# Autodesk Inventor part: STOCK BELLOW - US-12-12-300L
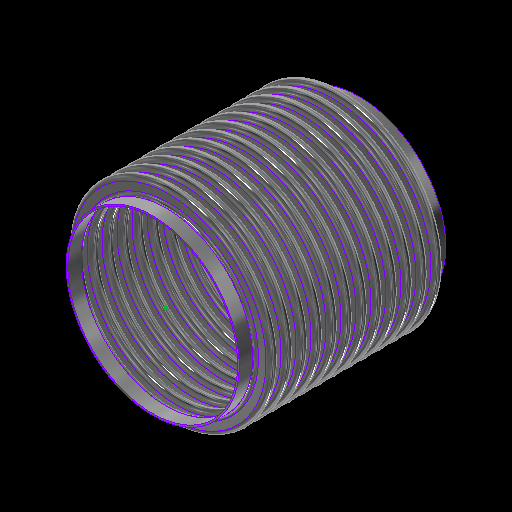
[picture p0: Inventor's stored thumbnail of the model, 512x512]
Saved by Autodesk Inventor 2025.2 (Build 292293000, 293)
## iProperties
Category: 16 GA (0.060 THICK)
RuleStatus: InUse
Created: 2024-01
Part Number: STOCK BELLOW - US-12-12-300L
Project: =STOCK BELLOWS: <Stock Number><SFILL>
Material: ASTM A240-304
Description: =STOCK BELLOWS: <Stock Number>, <SID_> I.D., <SOD_> O.D., <SPLY_> PLY, <Category>, <SNET_CONS> CONS.<PITCH_><STANGENT_> TANGENT<SFILL>
Document SubType Name: Sheet Metal
Designer: GS
Stock Number: U.S-12-12-300L
Surface Area: 20995.3 cm^2
Volume: 3171.06 cm^3
Sheet Metal Rule: Default
Appearance: STAINLESS STEEL
Mass: 25550.1 g
Density: 8.05729 g/cm^3
THK: 0.036
ID: 3.500
OD: 4.250
CONS_: 2
PITCH: 0.500
TANGENT: 0.500
BELLOWS_UPSET: 0.000
d79: 1.000
d82: 1.000
d83: 26.000
d84: 24.000
d174: 8
d214: 8
STHK_: 0.060
SID_: 12.750
SOD_: 15.250
SPITCH_: 1.125
STANGENT__: 1.000
SBELLOWS_UPSET_: 0.000
SDIFF_TAN: 1.000
d252: 2
d275: 2
d287: 0.050
d289: 0.500
d290: 0.000
SOD_NECK: 13
PLY: 1
PSET: 4.178
PBAR: 1.035
COUNTER: 1.500
NET_TUBE: 3.071
CONS: 2
S_CONS: 0
NET_CONS: 2
ID_M: 88.90 mm
OD_M: 107.95 mm
THK_M: 0.91 mm
ID_U: 3.500 in
OD_U: 4.250 in
THK_U: 0.036 in
TANGENT2: 0.500
TAN_TO_TAN: 1.000 in
d80: 2.571
d81: 10
SID: 2.375
SCONS_: 12
SPITCH: 0.250
STANGENT_: 1.000
SBELLOWS_UPSET: 0.000
SNET_CONS: 12
SS_CONS: 0
SCONS: 8
d190: 8
d191: 1
d192: 1
d193: 8
d194: 0
SIZE: 12.00
PRESSURE: 300
d230: 8
STANGENT: 4.000
SPLY_: 2
d233: 8
d234: 0
d263: 2
d265: 1
d268: 2
d269: 0
d286: 2
d288: 1
d291: 2
d292: 0
SREROLL: 0.750
BLETP: 1.000 ul
PRES_Copy: 85
MATTABLE: 20 GA (0.036 THICK)
PART_NUMBER: U.S-12-12-300L
PITCH_: =, <SPITCH_> PITCH,
CFILL: .
SFILL: .
MESH: ,
COMP: 2.36
EXT: 1.18
LAT: 0.76
ANG: 573
ASR: 4950
LSR: 7985
ANSR: 2116
PRES: 300
COMPM: 23.6
EXTM: 11.8
LATM: 7.60
ASRM: 866.894
PRESM: 20.684
LSRM: 1398.413
ANSRM: 370.575
TEMPMIN: 20
TEMPMAX: 800
TEMPMINM: -7
TEMPMAXM: 427
WEIGHTM: 25.550
WEIGHT: 56.328
Author: GS
Keywords: 20 GA (0.036 THICK)
Comments: =STOCK BELLOW - <STOCK NUMBER>
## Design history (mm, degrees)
sketch "Sketch2"
  geometry: L1 (0, -177.245)-(0, 562.856) reference; L2 (45.364, 0)-(44.45, 0); L3 (48.082, -2.718)-(50.343, -2.718); L4 (48.082, -3.632)-(50.343, -3.632); L5 (50.343, -9.982)-(48.082, -9.982); L6 (50.343, -9.068)-(48.082, -9.068); L7 (45.364, -12.7)-(44.45, -12.7); L8 (48.082, 0)-(48.082, -12.7); L9 (50.343, -6.35)-(53.975, -6.35); L10 (44.45, 0)-(44.45, -12.7); L11 (20.376, 102.841)-(20.376, 101.926); L12 (58.262, 457.127)-(58.262, 349.177); L13 (58.262, 444.427)-(58.262, 336.477); L14 (93.133, -58.817)-(93.133, -71.517); L15 (118.746, -66.401)-(118.746, -66.401); L16 (50.343, -9.068)-(50.343, -9.982); L17 (48.082, -9.068)-(48.082, -9.982); L18 (48.082, -9.525)-(50.343, -9.525); L19 (53.975, 0)-(53.975, -12.7); L20 (-50.343, -9.068)-(-50.343, -9.982); L21 (-50.343, -2.718)-(-48.082, -2.718); L22 (-50.343, -3.632)-(-48.082, -3.632); L23 (-48.082, -9.068)-(-50.343, -9.068); L24 (-50.343, -9.525)-(-48.082, -9.525); L25 (-48.082, -9.982)-(-50.343, -9.982); L26 (-48.082, -9.068)-(-48.082, -9.982); L27 (-44.45, 0.653)-(-44.45, -12.047); L28 (-48.082, -6.35)-(-44.45, -6.35); L29 (-50.343, 0.653)-(-50.343, -12.7); L30 (-53.061, 0)-(-53.975, 0); L31 (-53.975, 0)-(-53.975, -12.7); L32 (-53.061, -12.7)-(-53.975, -12.7); A1 r 2.718 centre (48.082, 0) between (45.364, 0) and (48.082, -2.718); A2 r 3.632 centre (48.082, 0) between (44.45, 0) and (48.082, -3.632); A3 r 3.632 centre (50.343, -6.35) between (50.343, -9.982) and (50.343, -2.718); A4 r 2.718 centre (50.343, -6.35) between (50.343, -9.068) and (50.343, -3.632); A5 r 2.718 centre (48.082, -12.7) between (48.082, -9.982) and (45.364, -12.7); A6 r 3.632 centre (48.082, -12.7) between (48.082, -9.068) and (44.45, -12.7); A7 r 3.175 centre (50.343, -6.35) between (50.343, -9.525) and (53.518, -6.35); A8 r 3.175 centre (48.082, -12.7) between (48.082, -9.525) and (44.907, -12.7); A9 r 2.718 centre (-50.343, -12.7) between (-50.343, -9.982) and (-53.061, -12.7); A10 r 2.718 centre (-48.082, -6.35) between (-48.082, -9.068) and (-48.082, -3.632); A11 r 3.175 centre (-48.082, -6.35) between (-48.082, -9.525) and (-44.907, -6.35); A12 r 3.632 centre (-48.082, -6.35) between (-48.082, -9.982) and (-48.082, -2.718); A13 r 3.175 centre (-50.343, -12.7) between (-50.343, -9.525) and (-53.518, -12.7); A14 r 3.632 centre (-50.343, -12.7) between (-50.343, -9.068) and (-53.975, -12.7); A15 r 2.718 centre (-50.343, 0) between (-53.061, 0) and (-50.343, -2.718); A16 r 3.632 centre (-50.343, 0) between (-53.975, 0) and (-50.343, -3.632); 10 further points
  constraints: 62 end point, 38 point on circle, 20 tangent, 16 centre point, 12 parallel, 9 midpoint, 7 vertical, 6 coincident, 6 concentric, 6 point on line, 4 equal radius, 4 perpendicular, 3 horizontal, 1 collinear, 1 horizontal alignment, 10 other
  dimensions: "THK" = 0.9144 distance of L11.start L11.end; "ID" = 88.9 distance of L11.end point (20.376, 13.026); "OD" = 107.95 distance of L12.start L12.end; "PITCH" = 12.7 distance of L12.start L13.start; "TANGENT" = 12.7 distance of L14.start L14.end; "BELLOWS_UPSET" = 0 distance of L15.start L15.end; "d43" = 88.9 diameter of L10 L1 (= ID); "d44" = 107.95 diameter of L9.end L1 (= OD); "d45" = 0.9144 distance between parallel lines of L5 L6 (computed from THK, PLY); "d46" = 3.6322 radius of A3 (computed from PITCH, THK, PLY); "UPSET_PITCH" = 12.7 distance of L2.end L7.end (derived); "SIDEWALL_ANGLE" = 360 deg dimension on L3 L9 (derived); "CON_GAP" = 5.4356 distance of point (48.082, -9.068) point (48.082, -3.632) (derived); "TAN1" = 4.98728 dimension on A8 (derived); "TAN2" = 4.98728 dimension on A7 (derived); "LEG1" = 2.2606 distance of L18.start L18.end (derived); "d278" = 0.9144 distance between parallel lines of L25 L23 (derived); "d279" = 3.6322 radius of A12 (derived); "d280" = 12.7 distance of L30.end L31.end (derived); "d281" = 360 deg dimension on L21 L28 (derived); "d282" = 5.4356 distance of point (-50.343, -9.068) point (-50.343, -3.632) (derived); "d283" = 4.98728 dimension on A13 (derived); "d284" = 4.98728 dimension on A11 (derived); "d285" = 2.2606 distance of L24.start L24.end (derived); "d293" = 88.9 diameter of L27 L1 (derived); "d294" = 107.95 diameter of L31 L1 (derived)
  node "Sketch Rectangular Pattern1" dims "d31" = 25.4, "ID" = 88.9
  node "Sketch Rectangular Pattern2" dims "d39" = 25.4, "PITCH" = 12.7
revolve "CONS" stored, may be unused: angle "d48" = 90 deg
node "BELLOW MIDPLANE"
pattern_linear "Rectangular Pattern2" dims "d52" = 12.7 (= UPSET_PITCH)
sketch "Sketch5"
  geometry: C1 r 45.364 at (0, 0) reference; C2 r 44.45 at (0, 0) reference
extrude "TANGENT" new body sketch "Sketch5" distance "d53" = 12.7 (= TANGENT); taper "d54" = 0 deg
revolve "SAMETAN" stored, may be unused: angle "d65" = 90 deg
revolve "DIFFTAN" stored, may be unused: angle "d70" = 90 deg
sketch "Sketch9"
  geometry: L1 (53.319, 0)-(-53.319, 0) reference; L2 (0, -17.78)-(0, 17.78) reference; L3 (38.085, 0)-(-38.085, 0); L4 (38.085, -11.906)-(38.085, 11.906); L5 (25.385, -11.906)-(25.385, 11.906); L6 (13.15, 11.906)-(13.15, -11.906); L7 (-25.385, -11.906)-(-25.385, 11.906); L8 (-38.085, -11.906)-(-38.085, 11.906); L9 (37.291, -11.906)-(37.291, 11.906); L10 (38.085, -11.906)-(37.291, -11.906); L11 (38.085, 11.906)-(37.291, 11.906); L12 (13.546, 11.906)-(12.753, 11.906); L13 (12.753, 11.906)-(12.753, -11.906); L14 (12.753, -11.906)-(13.546, -11.906); L15 (13.546, -11.906)-(13.546, 11.906); L16 (-13.546, 11.906)-(-13.546, -11.906); L17 (-13.15, 11.906)-(-13.15, -11.906); L18 (-13.546, -11.906)-(-12.753, -11.906); L19 (-12.753, -11.906)-(-12.753, 11.906); L20 (-12.753, 11.906)-(-13.546, 11.906); L21 (-38.085, -11.906)-(-37.291, -11.906); L22 (-37.291, -11.906)-(-37.291, 11.906); L23 (-37.291, 11.906)-(-38.085, 11.906); L24 (-38.085, 11.906)-(-38.085, -11.906); L25 (38.085, -0.397)-(-38.085, -0.397); L26 (-38.085, -0.397)-(-38.085, 0.397); L27 (-38.085, 0.397)-(38.085, 0.397); L28 (38.085, 0.397)-(38.085, -0.397); L29 (-38.085, 11.906)-(38.085, 11.906); L30 (38.085, 11.906)-(38.085, 12.7); L31 (38.085, 12.7)-(-38.085, 12.7); L32 (-38.085, 12.7)-(-38.085, 11.906); L33 (38.085, -11.906)-(-38.085, -11.906); L34 (-38.085, -11.906)-(-38.085, -12.7); L35 (-38.085, -12.7)-(38.085, -12.7); L36 (38.085, -12.7)-(38.085, -11.906); 30 further points
  constraints: 68 end point, 13 midpoint, 13 parallel, 8 horizontal, 7 perpendicular, 6 equal length, 3 point on line, 2 vertical, 14 other
  dimensions: "d115" = 23.8125 distance of L4.start L4.end (derived); "d116" = 12.7 distance between parallel lines of L4 L5 (derived); "d117" = 12.23516 distance between parallel lines of L5 L6 (derived); "d125" = 38.53427 distance between parallel lines of L7 L6 (derived); "d127" = 12.7 distance between parallel lines of L8 L7 (derived); "d128" = 24.93516 distance between parallel lines of L6 L4 (derived); "d130" = 76.16943 distance between parallel lines of L8 L4 (derived); "RULER_THK" = 0.79375 distance between parallel lines of L4 L9; "d135" = 0.79375 distance of L13.end L14.end (derived); "d138" = 26.29911 distance of L13.end L16.end (derived); "d143" = 0.79375 distance of L22.end L8.end (derived); "d144" = 0.79375 distance between parallel lines of L27 L25 (derived)
extrude "RULER" join sketch "Sketch9" distance "d149" = 0.79375 (derived); taper "d150" = 0 deg
extrude "BARS" join sketch "Sketch9" distance "d151" = 0.79375 (derived); taper "d152" = 0 deg
pattern_linear "Rectangular Pattern4" dims "d155" = 26.29911 (derived)
sketch "Sketch13"
  geometry: L1 (93.149, -52.467)-(93.149, -77.867); L2 (164.973, 0)-(161.925, 0); L3 (164.973, -28.575)-(161.925, -28.575); L4 (185.007, -22.955)-(170.593, -22.955); L5 (185.007, -19.907)-(170.593, -19.907); L6 (185.007, -14.287)-(193.675, -14.288); L7 (170.593, -5.62)-(185.007, -5.62); L8 (170.593, 0)-(170.593, -28.575); L9 (161.925, 0)-(161.925, -28.575); L10 (58.254, -109.081)-(58.254, -496.431); L11 (58.254, -137.656)-(58.254, -525.006); L12 (58.254, -194.806)-(58.254, -582.156); L13 (58.254, -223.381)-(58.254, -610.731); L14 (58.254, -251.956)-(58.254, -639.306); L15 (58.254, -280.531)-(58.254, -667.881); L16 (58.254, -309.106)-(58.254, -696.456); L17 (58.254, -166.231)-(58.254, -553.581); L18 (20.376, 103.45)-(20.376, 101.926); L19 (170.593, -8.668)-(185.007, -8.668); L20 (0, -856.437)-(0, 263.431) reference; L21 (-38.735, 0)-(232.41, 0) reference; A1 r 5.62 centre (170.593, 0) between (164.973, 0) and (170.593, -5.62); A2 r 5.62 centre (170.593, -28.575) between (170.593, -22.955) and (164.973, -28.575); A3 r 8.668 centre (170.593, -28.575) between (170.593, -19.907) and (161.925, -28.575); A4 r 5.62 centre (185.007, -14.287) between (185.007, -19.907) and (185.007, -8.668); A5 r 8.668 centre (185.007, -14.287) between (185.007, -22.955) and (185.007, -5.62); A6 r 8.668 centre (170.593, 0) between (161.925, 0) and (170.593, -8.668); 6 further points; 1 other entity
  constraints: 38 end point, 15 point on circle, 9 tangent, 6 centre point, 6 parallel, 5 vertical alignment, 4 point on line, 4 vertical, 3 coincident, 3 concentric, 2 collinear, 2 equal radius, 1 horizontal, 1 perpendicular, 23 other
  dimensions: "SBELLOWS_UPSET_" = 0 distance of point (118.762, -66.401) point (118.762, -66.401); "STOTAL_THK_BELLOW__" = 3.048 distance between parallel lines of L4 L5 (derived); "d224" = 8.66775 radius of A5 (derived); "d225" = 28.575 distance of L2.end L3.end (derived); "SSIDEWALL_ANGLE_" = 360 deg dimension on L7 L6 (derived); "SSCON_GAP_" = 11.2395 distance of point (170.593, -19.907) point (170.593, -8.668) (derived); "d235" = 323.85 diameter of L9 L20 (derived); "d236" = 387.35 diameter of L6.end L20 (derived)
  node "Sketch Rectangular Pattern4" dims "d228" = 25.4
  node "Sketch Rectangular Pattern5" dims "d229" = 25.4
revolve "SBELLOW" stored, may be unused: angle "d197" = 90 deg
pattern_linear "Rectangular Pattern5" dims "d204" = 28.575 (derived)
revolve "STANGENT" stored, may be unused: angle "d240" = 90 deg
revolve "SSAMETAN" stored, may be unused: angle "d241" = 90 deg
revolve "SDIFFTAN" stored, may be unused: angle "d246" = 90 deg
revolve "INVCON" stored, may be unused: angle "d295" = 90 deg
pattern_linear "Rectangular Pattern6" dims "d298" = 12.7 (derived)
revolve "INVTANGENT" stored, may be unused: angle "d302" = 90 deg
revolve "INVSAMETAN" stored, may be unused: angle "d307" = 90 deg
revolve "INVDIFFTAN" stored, may be unused: angle "d312" = 90 deg
sketch "ID BELLOW MOUNT CALC"
  geometry: L1 (44.45, 0)-(38.1, 0); L2 (38.1, 0)-(38.1, 12.7); L3 (38.1, 12.7)-(44.45, 12.7); L4 (44.45, 12.7)-(44.45, 0); L5 (36.513, 12.7)-(35.598, 12.7); L6 (35.598, 12.7)-(35.598, 0); L7 (35.598, 0)-(36.513, 0); L8 (36.513, 0)-(36.513, 12.7); L9 (0, -2.54)-(0, 15.24) reference; L10 (-8.89, 0)-(53.34, 0) reference; 1 further point
  constraints: 16 end point, 5 parallel, 2 collinear, 2 horizontal, 2 perpendicular
  dimensions: "d314" = 12.7 distance of L5.end L6.end (derived); "d315" = 0.9144 distance of L5.start L5.end (derived); "IG" = 1.5875 distance between parallel lines of L2 L8; "PIPE_OD" = 88.9 diameter of L4 L9; "PIPE_WALL" = 6.35 distance of L2.end L3.end; "ID_MT_BELLOW" = 71.1962 diameter of L6 L9 (derived)
revolve "CFILL" stored, may be unused: angle "d320" = 90 deg
pattern_linear "Rectangular Pattern7" dims "d323" = 12.7 (derived)
revolve "SFILL" stored, may be unused: angle "d324" = 90 deg
pattern_linear "Rectangular Pattern8" dims "d327" = 28.575 (derived)
node "STOCK BELLOW MIDPLANE"
node "BELLOW"
sketch "Sketch6"
  geometry: L1 (-12.7, 45.364)-(0, 45.364); L2 (0, 45.364)-(0, 44.45); L3 (0, 44.45)-(-12.7, 44.45); L4 (-12.7, 44.45)-(-12.7, 45.364); L5 (10.16, 0)-(-60.96, 0) reference; L6 (-38.1, -89.422)-(-38.1, 153.44) reference; 1 further point
  constraints: 8 end point, 2 parallel, 1 horizontal, 1 perpendicular
  dimensions: "d61" = 12.7 distance of L2.end L3.end (derived); "d62" = 0.9144 distance of L1.end L2.end (derived); "d63" = 88.9 diameter of L3 L5 (derived); "d64" = 25.4 distance between parallel lines of L4 L6 (derived)
sketch "Sketch12"
  geometry: 1 further point
sketch "Sketch14"
  geometry: L1 (-25.4, 164.973)-(0, 164.973); L2 (0, 164.973)-(0, 161.925); L3 (0, 161.925)-(-25.4, 161.925); L4 (-25.4, 161.925)-(-25.4, 164.973); L5 (5.08, 0)-(-30.48, 0) reference; L6 (0, -32.995)-(0, 197.968) reference; 1 further point
  constraints: 8 end point, 2 parallel, 1 collinear, 1 horizontal, 1 perpendicular
  dimensions: "d237" = 3.048 distance of L3.end L1.start (derived); "d238" = 323.85 diameter of L3 L5 (derived); "d239" = 25.4 distance of L1.start L1.end (derived); "SOD_NECK" = 329.946 diameter of L1 L5 (derived)
sketch "Sketch15"
  geometry: L1 (-32.995, 0)-(197.968, 0) reference; L2 (161.925, -342.9)-(164.973, -342.9); L3 (164.973, -342.9)-(164.973, -368.3); L4 (164.973, -368.3)-(161.925, -368.3); L5 (161.925, -368.3)-(161.925, -342.9); L6 (0, -444.5)-(0, 88.9) reference; 1 further point
  constraints: 8 end point, 2 parallel, 1 horizontal, 1 perpendicular
  dimensions: "d205" = 25.4 distance of L4.end L2.start (derived); "d206" = 3.048 distance of L3.end L4.end (derived); "d207" = 323.85 diameter of L5 L6 (derived); "d208" = 342.9 distance between parallel lines of L1 L2 (derived)
node "TANGENT_"
node "SAME_TAN"
sketch "Sketch8"
  geometry: L1 (45.364, -25.4)-(44.45, -25.4); L2 (44.45, -25.4)-(44.45, -38.1); L3 (44.45, -38.1)-(45.364, -38.1); L4 (45.364, -38.1)-(45.364, -25.4); L5 (0, -48.26)-(0, 22.86) reference; L6 (-89.422, 0)-(153.44, 0) reference; 1 further point
  constraints: 8 end point, 2 parallel, 1 horizontal, 1 perpendicular
  dimensions: "d66" = 88.9 diameter of L2 L5 (derived); "TOTAL_THK_BELLOW" = 0.9144 distance of L2.end L3.end (derived); "d68" = 25.4 distance between parallel lines of L1 L6 (derived); "d69" = 12.7 distance of L1.end L2.end (derived)
node "DIFF_TAN"
node "Sketch Rectangular Pattern3" dims "d138" = 26.29911 (derived), "d141" = 25.4
node "SBELLOW_"
node "STANGENT_"
node "SSAME_TAN"
sketch "Sketch16"
  geometry: L1 (164.973, -342.9)-(161.925, -342.9); L2 (161.925, -342.9)-(161.925, -368.3); L3 (161.925, -368.3)-(164.973, -368.3); L4 (164.973, -368.3)-(164.973, -342.9); L5 (0, -444.5)-(0, 88.9) reference; L6 (-32.995, 0)-(197.968, 0) reference; 1 further point
  constraints: 8 end point, 2 parallel, 1 horizontal, 1 perpendicular
  dimensions: "SDIFF_TAN" = 25.4 distance of L3.end L1.start; "d243" = 3.048 distance of L2.end L3.end (derived); "d244" = 342.9 distance between parallel lines of L1 L6 (derived); "d245" = 323.85 diameter of L2 L5 (derived)
node "SDIFF_TAN"
body "Solid15"
sketch "Sketch17"
  geometry: L1 (53.975, 12.7)-(53.061, 12.7); L2 (53.061, 12.7)-(53.061, 0); L3 (53.061, 0)-(53.975, 0); L4 (53.975, 0)-(53.975, 12.7); L5 (0, -2.54)-(0, 15.24) reference; L6 (-10.795, 0)-(64.77, 0) reference; 2 further points
  constraints: 8 end point, 2 parallel, 1 horizontal, 1 midpoint, 1 perpendicular, 1 point on line
  dimensions: "INVTANGENT" = 12.7 distance of L3.end L1.start (derived); "d300" = 0.9144 distance of L1.start L1.end (derived); "d301" = 107.95 diameter of L4 L5 (derived)
body "Solid16"
sketch "Sketch18"
  geometry: L1 (53.975, -25.4)-(53.061, -25.4); L2 (53.061, -25.4)-(53.061, -38.1); L3 (53.061, -38.1)-(53.975, -38.1); L4 (53.975, -38.1)-(53.975, -25.4); L5 (-10.795, 0)-(64.77, 0) reference; L6 (0, -48.26)-(0, 22.86) reference; 1 further point
  constraints: 8 end point, 2 parallel, 1 horizontal, 1 perpendicular
  dimensions: "d303" = 25.4 distance between parallel lines of L1 L5 (derived); "d304" = 12.7 distance of L3.end L1.start (derived); "d305" = 0.9144 distance of L2.end L3.end (derived); "d306" = 107.95 diameter of L4 L6 (derived)
body "Solid17"
sketch "Sketch19"
  geometry: L1 (53.975, -25.4)-(53.061, -25.4); L2 (53.061, -25.4)-(53.061, -38.1); L3 (53.061, -38.1)-(53.975, -38.1); L4 (53.975, -38.1)-(53.975, -25.4); L5 (0, -48.26)-(0, 22.86) reference; L6 (-10.795, 0)-(64.77, 0) reference; 1 further point
  constraints: 8 end point, 2 parallel, 1 horizontal, 1 perpendicular
  dimensions: "d308" = 12.7 distance of L1.end L2.end (derived); "d309" = 107.95 diameter of L4 L5 (derived); "d310" = 0.9144 distance of L2.end L3.end (derived); "d311" = 25.4 distance between parallel lines of L1 L6 (derived)
body "Solid18"
body "Solid19"
body "Solid20"
other parameters: "BMPL" = -171.45, "PSET" = 106.1212 (computed from OD, THK, PLY) [user parameter], "PBAR" = 26.29911 (= 0.570796 x PITCH + OD - ID) [user parameter; used in 1 equation term], "COUNTER" = 15 [user parameter], "NET_TUBE" = 77.99823 (computed from CONS_, PBAR, TANGENT) [user parameter], "S_CONS" = 0 [user parameter; used in 1 equation term], "ID_M" = 88.9 (= ID) [user parameter], "OD_M" = 107.95 (= OD) [user parameter], "THK_M" = 0.9144 (= THK) [user parameter], "ID_U" = 88.9 (= ID) [user parameter], "OD_U" = 107.95 (= OD) [user parameter], "THK_U" = 0.9144 (= THK) [user parameter], "D_UNITS" = 0 [user parameter], "TANGENT2" = 12.7 [user parameter], "TAN_TO_TAN" = 25.4 [user parameter], "OD_NECK" = 90.7288 [user parameter], "d79" = 25.4, "d80" = 65.29823 [user parameter], "d82" = 25.4, "d83" = 660.4, "d84" = 609.6, "sa_0" = 4, "FRAME_THK" = 0.79375 [user parameter], "CON_FLAT" = 12.23516 [user parameter], "SID" = 60.325 [user parameter], "SPITCH" = 6.35 [user parameter], "STANGENT_" = 25.4 [user parameter], "SBELLOWS_UPSET" = 0 [user parameter], "SS_CONS" = 0 [user parameter], "STAN_TO_TAN_" = 342.9 [user parameter], "d100" = 3.048 [user parameter], "d191" = 25.4 [user parameter], "d194" = 0 [user parameter], "STANGENT" = 101.6 [user parameter], "d234" = 0 [user parameter], "SUPSET_PITCH_" = 28.575 [user parameter], "d269" = 0 [user parameter], "d287" = 1.27, "d289" = 12.7, "d290" = 0, "d292" = 0 [user parameter], "Thickness" = 3.048 (derived), "KFactor" = 4.4, "BendRadius" = 3.048 (derived), "BendReliefWidth" = 3.048 (derived), "BendReliefDepth" = 1.524 (derived), "CornerReliefSize" = 12.192 (derived), "SeamGap" = 0.00508, "MinimumRemnant" = 6.096 (derived), "TransitionRadius" = 3.048 (derived), "JacobiRadiusSize" = 3.048 (derived), "GapSize" = 3.048 (derived), "SREROLL" = 19.05 [user parameter], "CUR_STK_PITCH" = 28.575 [user parameter], "d328" = -171.45 (derived), "ASR" = 49500 [user parameter], "LSR" = 79850 [user parameter], "ANSR" = 21160 [user parameter], "BLETP" = 1 [user parameter], "ASRM" = 8668.935 [user parameter], "PRESM" = 206.83949 [user parameter], "LSRM" = 13984.1305 [user parameter], "ANSRM" = 3705.7508 [user parameter], "TEMPMIN" = 2664.83333 [user parameter], "TEMPMAX" = 6998.16667 [user parameter], "TEMPMINM" = 2664.83333 [user parameter], "TEMPMAXM" = 6998.16667 [user parameter], "WEIGHT" = 255.50111 [user parameter], "WEIGHTM" = 0.2555 [user parameter]
